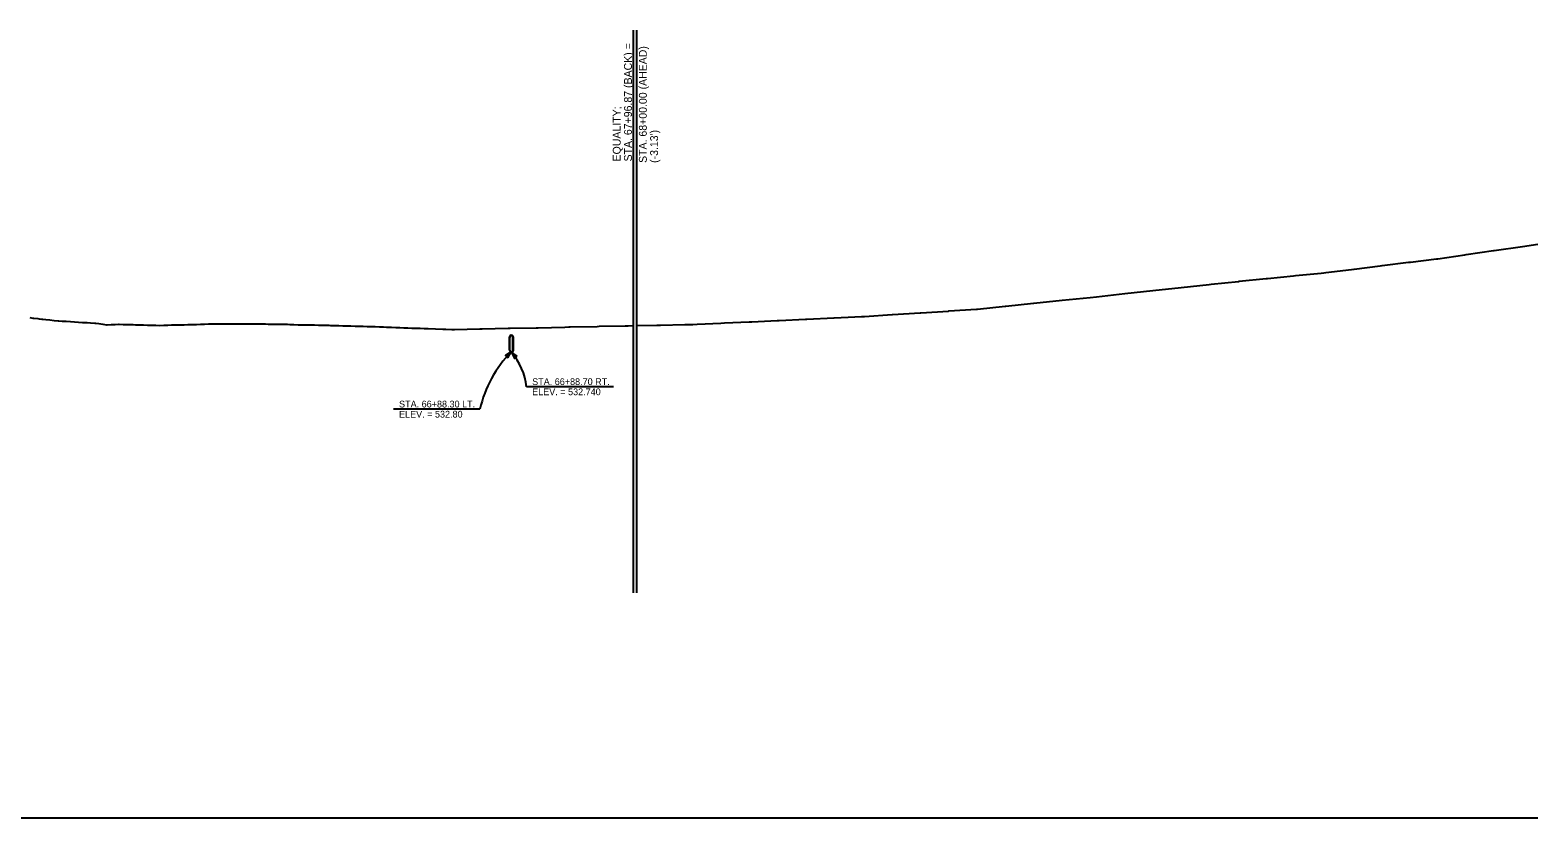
# Model space of a CAD drawing. Extents: x 49922 to 52613, y 49991 to 60509.
# Drawn here: x 51261 to 52600, y 52500 to 53200 of the extents above; entities that cross this region are included whole.
import ezdxf

# ---------------------------------------------------------------- set-up
doc = ezdxf.new("R2010")
doc.units = 0
for name, color, linetype in [('RD_DDB_Profile_EX', 7, 'Continuous'), ('RD_DDB_VCLbl', 7, 'Continuous'), ('RD_GPK_Profile_Cell', 7, 'Continuous'), ('RD_Sketch2', 7, 'Continuous'), ('RD_TX_Profile', 7, 'Continuous')]:
    doc.layers.add(name, color=color, linetype=linetype)

msp = doc.modelspace()

# ---------------------------------------------------------------- linework, layer by layer
at = {"layer": 'RD_DDB_Profile_EX'}
for points in [[(51800, 52937.4), (51817.6, 52937.8), (51820.9, 52937.8), (51842.6, 52938.3), (51843.6, 52938.3), (51849.5, 52938.4), (51853.4, 52938.6), (51874.5, 52939.6), (51877.8, 52939.8), (51899.6, 52940.8), (51902.1, 52940.9), (51924.6, 52942), (51926.4, 52942.1), (51949.6, 52943.2), (51950.7, 52943.2), (51974.7, 52944.4), (51975, 52944.4), (51987.6, 52945), (51999.4, 52945.5), (51999.7, 52945.5), (52002, 52945.6), (52026.6, 52947.2), (52027, 52947.2), (52051.6, 52948.8), (52052, 52948.8), (52076.6, 52950.4), (52077, 52950.5), (52101.6, 52952), (52102, 52952.1), (52102.5, 52952.1), (52127.1, 52954.7), (52127.5, 52954.7), (52152.2, 52957.3), (52152.5, 52957.3), (52177.5, 52959.9), (52202.5, 52962.5), (52208.2, 52963.1), (52233.2, 52965.9), (52258.2, 52968.6), (52283.2, 52971.4), (52308.1, 52974.1), (52309.8, 52974.3), (52334.1, 52976.7), (52334.9, 52976.8), (52358.6, 52979.2), (52359.9, 52979.3), (52383, 52981.7), (52384.9, 52981.9), (52407.5, 52984.1), (52410, 52984.4), (52411.8, 52984.6), (52434.6, 52987.4), (52436.8, 52987.7), (52459.9, 52990.5), (52461.8, 52990.8), (52485.2, 52993.7), (52486.8, 52993.9), (52510, 52996.7), (52511.2, 52996.9), (52535.3, 53000.4), (52536.2, 53000.5), (52560.6, 53004.1), (52561.2, 53004.2), (52586.3, 53007.8), (52600, 53009.9)], [(51260.7, 52944.5), (51263.6, 52944.1), (51264.3, 52944), (51267.9, 52943.7), (51269.1, 52943.6), (51271.5, 52943.3), (51272.4, 52943.2), (51275.1, 52942.9), (51278.7, 52942.5), (51282.3, 52942.1), (51285.9, 52941.7), (51286.7, 52941.7), (51289.6, 52941.5), (51293.2, 52941.3), (51296.8, 52941), (51300.4, 52940.8), (51304, 52940.6), (51307.6, 52940.3)], [(51307.6, 52940.3), (51310.6, 52940.1), (51311.2, 52940.1), (51311.6, 52940.1), (51314.8, 52939.8), (51318.5, 52939.6), (51319.4, 52939.5), (51322.1, 52939.2), (51325.7, 52938.6), (51328.8, 52938.1), (51329.4, 52938.1), (51332.9, 52938.3), (51336.5, 52938.5), (51339.7, 52938.6), (51340.1, 52938.6), (51343.7, 52938.5), (51347.3, 52938.4), (51351, 52938.3), (51352.6, 52938.3), (51354.6, 52938.2), (51358.2, 52938.1), (51361.8, 52938), (51365.4, 52937.9), (51369, 52937.8), (51372.6, 52937.7), (51376.3, 52937.6), (51379.8, 52937.8), (51383.5, 52937.9), (51386.7, 52938), (51387.1, 52938), (51390.7, 52938.1), (51394.3, 52938.1), (51397.9, 52938.2), (51401.2, 52938.3), (51401.5, 52938.3), (51405.1, 52938.4), (51408.7, 52938.5), (51412.4, 52938.7), (51416, 52938.8), (51419.6, 52938.9), (51421.9, 52939), (51422.3, 52939), (51423.2, 52939), (51426.8, 52939), (51430.4, 52939), (51434, 52939), (51437.6, 52939), (51441.2, 52939), (51442.8, 52939), (51444.9, 52939), (51447.4, 52939), (51448.5, 52939), (51452.1, 52939), (51455.7, 52939), (51459.3, 52939), (51462.9, 52938.9), (51463.7, 52938.9), (51466.5, 52938.9), (51470.1, 52938.9), (51472.5, 52938.8), (51474, 52938.8), (51476.2, 52938.8), (51477.4, 52938.8), (51481, 52938.7), (51484.6, 52938.6), (51488.2, 52938.6), (51489.6, 52938.6), (51491.8, 52938.5), (51495.4, 52938.4), (51499, 52938.2), (51501.2, 52938.2), (51502.6, 52938.1), (51506.2, 52938.1), (51509.9, 52938), (51513.5, 52938), (51517.1, 52937.9), (51519.1, 52937.9), (51520.7, 52937.9), (51524.3, 52937.7), (51526.2, 52937.7), (51527.9, 52937.6), (51528.9, 52937.6), (51529.7, 52937.6), (51531.5, 52937.5), (51535.1, 52937.4), (51538.8, 52937.3), (51542.4, 52937.2), (51546, 52937.1), (51549.6, 52937), (51551, 52937), (51553.2, 52936.9), (51554.7, 52936.9), (51556.8, 52936.8), (51560.4, 52936.7), (51564, 52936.6), (51567.6, 52936.5), (51571.3, 52936.3), (51574.9, 52936.2), (51577.6, 52936.1), (51578.5, 52936.1), (51579.7, 52936.1)], [(51579.7, 52936.1), (51582.1, 52936), (51585.7, 52935.8), (51589.3, 52935.7), (51592.9, 52935.6), (51596.5, 52935.5), (51600.1, 52935.3), (51603, 52935.2), (51603.8, 52935.2), (51604.7, 52935.2), (51607.4, 52935.1), (51611, 52934.9), (51614.6, 52934.8), (51627.6, 52934.3), (51629.7, 52934.2), (51630.1, 52934.2), (51635.5, 52934), (51637.8, 52934.1), (51660.5, 52934.5), (51662.6, 52934.6), (51685.5, 52935.1), (51687.4, 52935.1), (51710.5, 52935.6), (51712.1, 52935.6), (51735.8, 52936.1), (51739.6, 52936.2), (51740.8, 52936.2), (51764.5, 52936.7), (51766.5, 52936.8), (51789.5, 52937.2), (51792.2, 52937.3), (51796.9, 52937.4)]]:
    msp.add_lwpolyline(points, dxfattribs=at)
at = {"layer": 'RD_DDB_VCLbl'}
for p, q in [((51796.9, 52937.4), (51796.9, 53200)), ((51800, 52700), (51800, 53200)), ((51796.9, 52700), (51796.9, 53033.4))]:
    msp.add_line(p, q, dxfattribs=at)
at = {"layer": 'RD_GPK_Profile_Cell'}
msp.add_line((50000, 52500), (52600, 52500), dxfattribs=at)
at = {"layer": 'RD_Sketch2'}
for p, q in [((51686.8, 52915.5), (51686.8, 52927.5)), ((51687.2, 52915.2), (51687.2, 52927.2)), ((51689.8, 52915.5), (51689.8, 52927.5)), ((51690.2, 52915.2), (51690.2, 52927.2))]:
    msp.add_line(p, q, dxfattribs=at)
for centre, start, end in [((51688.3, 52927.5), 360, 180), ((51688.7, 52927.2), 360, 180), ((51688.3, 52915.5), 180, 0), ((51688.7, 52915.2), 180, 0)]:
    msp.add_arc(centre, 1.5, start, end, dxfattribs=at)
at = {"layer": 'RD_TX_Profile'}
for p, q in [((51779.2, 52883.1), (51701.9, 52883.1)), ((51660.5, 52863.2), (51583.7, 52863.2))]:
    msp.add_line(p, q, dxfattribs=at)
for points in [[(51685.3, 52908.8), (51688.3, 52914), (51683.1, 52911)], [(51693.6, 52910.2), (51688.7, 52913.7), (51691.2, 52908.3)]]:
    msp.add_lwpolyline(points, close=True, dxfattribs=at)
for centre, radius, start, end in [((51762.3, 52840.6), 104.2, 135.2071, 167.4766), ((51643.6, 52876), 58.8, 6.9401, 39.8503)]:
    msp.add_arc(centre, radius, start, end, dxfattribs=at)

# ---------------------------------------------------------------- texts
for s, p in [('STA. 67+96.87 (BACK) =', (51795.5, 53083.3)), ('STA. 68+00.00 (AHEAD)', (51808.7, 53082)), ('EQUALITY;', (51785.5, 53083.3)), ("(-3.13')", (51818.7, 53082))]:
    msp.add_text(s, height=7, rotation=90, dxfattribs=at).set_placement(p)
for s, p in [('STA. 66+88.70 RT.', (51706.9, 52884.6)), ('ELEV. = 532.740', (51706.9, 52875.6)), ('STA. 66+88.30 LT.', (51588.7, 52864.7)), ('ELEV. = 532.80', (51588.7, 52855.7))]:
    msp.add_text(s, height=6, dxfattribs=at).set_placement(p)

doc.saveas('drawing.dxf')
